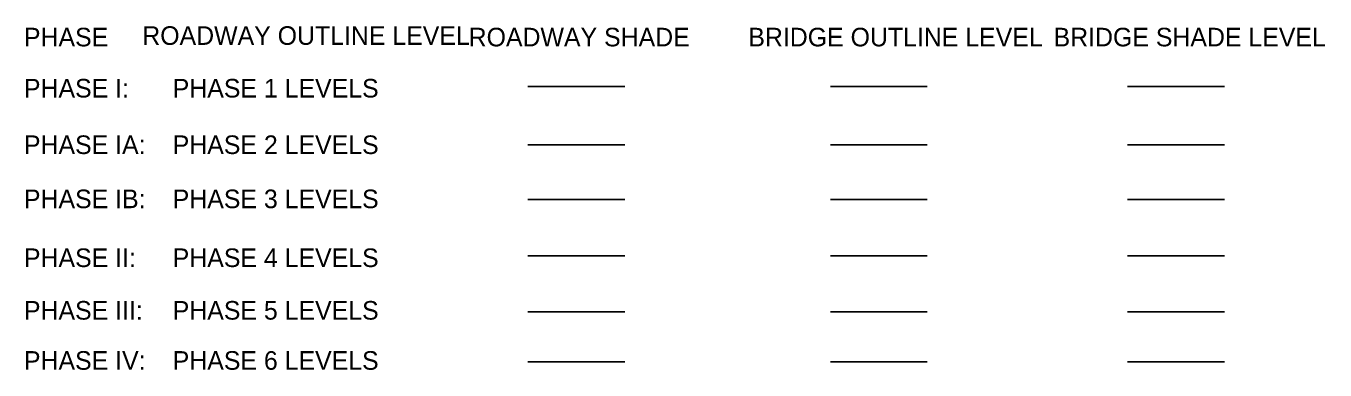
# Model space of a CAD drawing. Extents: x 2133551 to 2156187, y 140366 to 148242.
# Drawn here: x 2133551 to 2140536, y 145856 to 147707 of the extents above; entities that cross this region are included whole.
import ezdxf

# ---------------------------------------------------------------- set-up
doc = ezdxf.new("R2010")
doc.units = 0
for name, color, linetype in [('Default', 7, 'Continuous'), ('INR_InRoads_Unassigned', 7, 'Continuous'), ('MTL_Concrete', 7, 'Continuous'), ('PR_Align_2', 7, 'Continuous'), ('PR_Align_Ramp_A', 7, 'Continuous'), ('PR_Align_Ramp_B', 7, 'Continuous'), ('PR_Align_Ramp_D', 7, 'Continuous'), ('PR_Align_Ramp_H', 7, 'Continuous'), ('PR_Align_Ramp_M', 7, 'Continuous'), ('PR_Align_Retaining_Wall_D_PI_Curve', 7, 'Continuous'), ('PR_Curb_Back', 7, 'Continuous'), ('PR_Curb_Face', 7, 'Continuous'), ('PR_Curb_Top', 7, 'Continuous'), ('PR_DTM_Exterior', 7, 'Continuous'), ('PR_Parapet', 7, 'Continuous'), ('PR_Phasing_Pavement_6', 7, 'Continuous'), ('PR_Retaining_Wall', 7, 'Continuous'), ('PR_Road_Shoulder', 7, 'Continuous'), ('PR_Sidewalk', 7, 'Continuous'), ('PR_Storm_Ditch_Paved', 7, 'Continuous'), ('PR_Storm_Ditch_Unpaved', 7, 'Continuous'), ('PR_Toe_of_Slope', 7, 'Continuous'), ('PR_Txt', 7, 'Continuous'), ('TMPL_Cut', 7, 'Continuous')]:
    doc.layers.add(name, color=color, linetype=linetype)

msp = doc.modelspace()

# ---------------------------------------------------------------- linework, layer by layer
msp.add_line((2138397.4, 146773.2), (2137876.7, 146773.2))
at = {"layer": 'INR_InRoads_Unassigned'}
msp.add_line((2136770.4, 146773.2), (2136249.8, 146773.2), dxfattribs=at)
at = {"layer": 'MTL_Concrete'}
msp.add_line((2138397.4, 145900.7), (2137876.7, 145900.7), dxfattribs=at)
at = {"layer": 'PR_Align_2'}
msp.add_line((2138397.4, 147381), (2137876.7, 147381), dxfattribs=at)
at = {"layer": 'PR_Align_Ramp_A'}
msp.add_line((2139995.4, 145900.7), (2139474.7, 145900.7), dxfattribs=at)
at = {"layer": 'PR_Align_Ramp_B'}
msp.add_line((2139995.4, 146169.5), (2139474.7, 146169.5), dxfattribs=at)
at = {"layer": 'PR_Align_Ramp_H'}
msp.add_line((2139995.4, 147381), (2139474.7, 147381), dxfattribs=at)
at = {"layer": 'PR_Align_Ramp_M'}
msp.add_line((2138397.4, 147066.7), (2137876.7, 147066.7), dxfattribs=at)
at = {"layer": 'PR_Align_Retaining_Wall_D_PI_Curve'}
msp.add_line((2136770.4, 146471.3), (2136249.8, 146471.3), dxfattribs=at)
at = {"layer": 'PR_DTM_Exterior'}
msp.add_line((2136770.4, 146169.5), (2136249.8, 146169.5), dxfattribs=at)
at = {"layer": 'PR_Parapet'}
msp.add_line((2138397.4, 146169.5), (2137876.7, 146169.5), dxfattribs=at)
at = {"layer": 'PR_Phasing_Pavement_6'}
msp.add_line((2139995.4, 146471.3), (2139474.7, 146471.3), dxfattribs=at)
at = {"layer": 'PR_Retaining_Wall'}
msp.add_line((2136770.4, 147381), (2136249.8, 147381), dxfattribs=at)
at = {"layer": 'PR_Sidewalk'}
msp.add_line((2136770.4, 145900.7), (2136249.8, 145900.7), dxfattribs=at)
at = {"layer": 'PR_Storm_Ditch_Paved'}
msp.add_line((2138397.4, 146471.3), (2137876.7, 146471.3), dxfattribs=at)
at = {"layer": 'PR_Toe_of_Slope'}
msp.add_line((2139995.4, 146773.2), (2139474.7, 146773.2), dxfattribs=at)
at = {"layer": 'PR_Txt'}
msp.add_line((2136770.4, 147066.7), (2136249.8, 147066.7), dxfattribs=at)
at = {"layer": 'TMPL_Cut'}
msp.add_line((2139995.4, 147066.7), (2139474.7, 147066.7), dxfattribs=at)

# ---------------------------------------------------------------- texts
at = {"layer": 'Default'}
for s, p in [('PHASE', (2133540, 147596.9)), ('ROADWAY OUTLINE LEVEL', (2134176.3, 147605.1)), ('ROADWAY SHADE', (2135931.4, 147596.9)), ('BRIDGE OUTLINE LEVEL', (2137435.4, 147596.9)), ('BRIDGE SHADE LEVEL', (2139076.8, 147596.9))]:
    msp.add_text(s, height=100, dxfattribs=at).set_placement(p)
at = {"layer": 'PR_Align_Ramp_D'}
for s, p in [('PHASE IB:', (2133540, 146726.7)), ('PHASE 3 LEVELS', (2134340, 146726.7))]:
    msp.add_text(s, height=100, dxfattribs=at).set_placement(p)
at = {"layer": 'PR_Curb_Back'}
for s, p in [('PHASE III:', (2133540, 146127.3)), ('PHASE 5 LEVELS', (2134340, 146127.3))]:
    msp.add_text(s, height=100, dxfattribs=at).set_placement(p)
at = {"layer": 'PR_Curb_Face'}
for s, p in [('PHASE IV:', (2133540, 145857.7)), ('PHASE 6 LEVELS', (2134340, 145857.7))]:
    msp.add_text(s, height=100, dxfattribs=at).set_placement(p)
at = {"layer": 'PR_Curb_Top'}
for s, p in [('PHASE IA:', (2133540, 147018)), ('PHASE 2 LEVELS', (2134340, 147018))]:
    msp.add_text(s, height=100, dxfattribs=at).set_placement(p)
at = {"layer": 'PR_Road_Shoulder'}
for s, p in [('PHASE I:', (2133540, 147321.9)), ('PHASE 1 LEVELS', (2134340, 147321.9))]:
    msp.add_text(s, height=100, dxfattribs=at).set_placement(p)
at = {"layer": 'PR_Storm_Ditch_Unpaved'}
for s, p in [('PHASE II:', (2133540, 146410.1)), ('PHASE 4 LEVELS', (2134340, 146410.1))]:
    msp.add_text(s, height=100, dxfattribs=at).set_placement(p)

doc.saveas('drawing.dxf')
